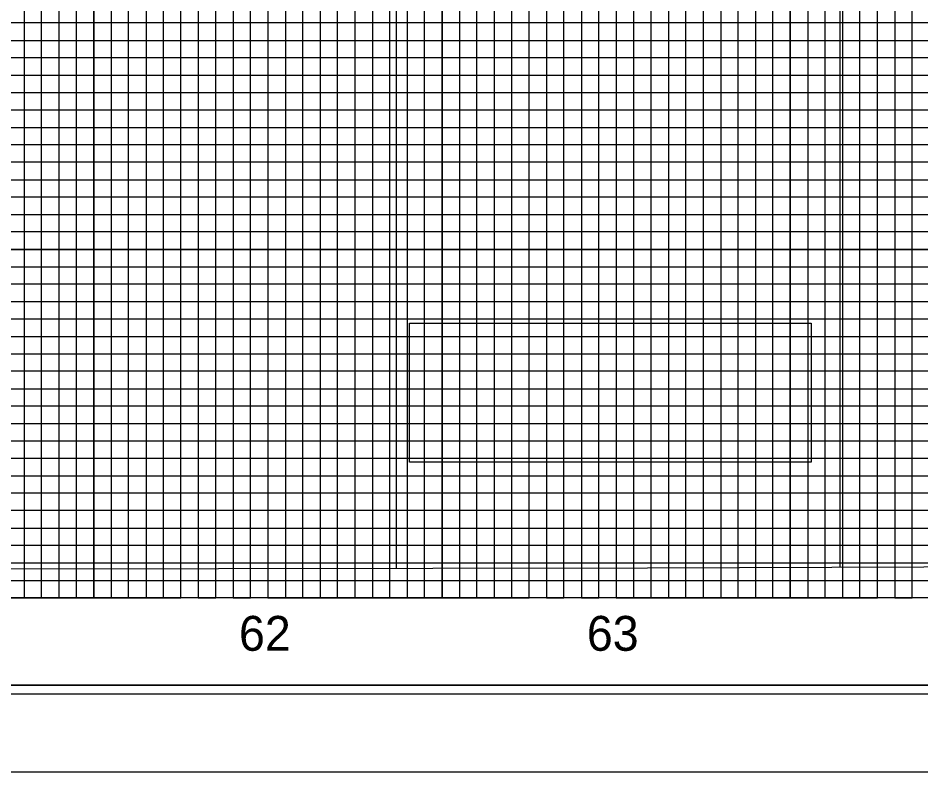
# Model space of a CAD drawing. Extents: x 557032 to 562069, y 513430 to 515874.
# Drawn here: x 558177.7 to 558437, y 514774.3 to 514990.7 of the extents above; entities that cross this region are included whole.
import ezdxf

# ---------------------------------------------------------------- set-up
doc = ezdxf.new("R2010")
doc.units = 0
for name, color, linetype in [('Exist Vertical Profile Horizontal Axis Label Major', 7, 'Continuous'), ('Prop Vertical Profile Curve Label', 7, 'Continuous'), ('Scratch_Level_1', 7, 'Continuous'), ('Scratch_Level_5', 7, 'Continuous'), ('Sheet Cutting Line CELL', 7, 'Continuous'), ('Sheet DOT Grid CELL', 7, 'Continuous'), ('Sheet Layout Profile Border Port 2', 7, 'Continuous'), ('Sheet Plot Border Inside CELL', 7, 'Continuous'), ('Sheet Plot Border Outside CELL', 7, 'Continuous'), ('Sheet Profile CELL', 7, 'Continuous'), ('Sheet Profile Grid Major CELL', 7, 'Continuous'), ('Sheet Profile Grid Middle CELL', 7, 'Continuous'), ('Sheet Profile Grid Minor CELL', 7, 'Continuous')]:
    doc.layers.add(name, color=color, linetype=linetype)

msp = doc.modelspace()

# ---------------------------------------------------------------- linework, layer by layer
at = {"layer": 'Prop Vertical Profile Curve Label'}
msp.add_lwpolyline([(558290.08, 514903.1), (558405.4, 514903.1), (558405.4, 514863.23), (558290.08, 514863.23)], close=True, dxfattribs=at)
at = {"layer": 'Scratch_Level_1'}
msp.add_line((558286.33, 514832.76), (558286.33, 515319), dxfattribs=at)
at = {"layer": 'Scratch_Level_5'}
msp.add_line((558413.73, 514833.08), (558413.73, 515318.28), dxfattribs=at)
msp.add_lwpolyline([(557249.45, 515324.28), (557249.45, 514824.28), (557239, 514812.71), (557236.95, 514799.28), (558647.93, 514799.13), (558699.45, 514799.28), (558649.45, 514824.28), (558649.45, 515324.28)], close=True, dxfattribs=at)
msp.add_lwpolyline([(557250.22, 514849.46), (558648.7, 514849.31), (558650.22, 514849.32)], dxfattribs=at)
at = {"layer": 'Sheet Cutting Line CELL'}
msp.add_line((557032.45, 514774.28), (558716.45, 514774.28), dxfattribs=at)
at = {"layer": 'Sheet DOT Grid CELL'}
for p, q in [((558199.45, 515324.28), (558199.45, 514824.28)), ((558249.45, 515324.28), (558249.45, 514824.28)), ((558299.45, 515324.28), (558299.45, 514824.28)), ((558349.45, 515324.28), (558349.45, 514824.28)), ((558399.45, 515324.28), (558399.45, 514824.28)), ((557199.45, 514974.28), (558699.34, 514974.28)), ((557199.45, 514924.28), (558699.34, 514924.28)), ((557199.45, 514874.28), (558699.34, 514874.28))]:
    msp.add_line(p, q, dxfattribs=at)
at = {"layer": 'Sheet Layout Profile Border Port 2'}
msp.add_lwpolyline([(557249.45, 515324.28), (558649.45, 515324.28), (558649.45, 514824.28), (557249.45, 514824.28)], close=True, dxfattribs=at)
msp.add_lwpolyline([(557249.45, 514831.1), (558358.41, 514832.88), (558649.45, 514833.95)], dxfattribs=at)
at = {"layer": 'Sheet Plot Border Inside CELL'}
msp.add_lwpolyline([(557045.45, 514796.73), (558711.95, 514796.73), (558711.95, 515851.83), (557045.45, 515851.83)], close=True, dxfattribs=at)
at = {"layer": 'Sheet Plot Border Outside CELL'}
msp.add_lwpolyline([(557032.45, 514774.28), (558716.45, 514774.28), (558716.45, 515874.28), (557032.45, 515874.28)], close=True, dxfattribs=at)
at = {"layer": 'Sheet Profile CELL'}
for p, q in [((558699.45, 514824.28), (557199.45, 514824.28)), ((557199.45, 514799.28), (558699.45, 514799.28))]:
    msp.add_line(p, q, dxfattribs=at)
msp.add_lwpolyline([(558699.45, 515849.28), (557199.45, 515849.28), (557199.45, 514799.28), (558699.45, 514799.28)], close=True, dxfattribs=at)
at = {"layer": 'Sheet Profile Grid Major CELL'}
for points in [[(558149.45, 514824.28), (558199.45, 514824.28), (558199.45, 515324.28), (558249.45, 515324.28), (558249.45, 514824.28), (558299.45, 514824.28), (558299.45, 515324.28), (558349.45, 515324.28), (558349.45, 514824.28), (558399.45, 514824.28), (558399.45, 515324.28), (558449.45, 515324.28), (558449.45, 514824.28), (558499.45, 514824.28), (558499.45, 515324.28), (558549.45, 515324.28), (558549.45, 514824.28), (558599.45, 514824.28), (558599.45, 514824.28), (558599.45, 514964.88)], [(558699.45, 515024.28), (557199.45, 515024.28), (557199.45, 514974.28), (558554.45, 514974.28)], [(558699.45, 514924.28), (557199.45, 514924.28), (557199.45, 514924.28), (557199.45, 514874.28), (558699.45, 514874.28)], [(558699.45, 514824.28), (557199.45, 514824.28)]]:
    msp.add_lwpolyline(points, dxfattribs=at)
at = {"layer": 'Sheet Profile Grid Middle CELL'}
for points in [[(558174.45, 514824.28), (558224.45, 514824.28), (558224.45, 515324.28), (558274.45, 515324.28), (558274.45, 514824.28), (558324.45, 514824.28), (558324.45, 515324.28), (558374.45, 515324.28), (558374.45, 514824.28), (558424.45, 514824.28), (558424.45, 515324.28), (558474.45, 515324.28), (558474.45, 514824.28), (558524.45, 514824.28), (558524.45, 515324.28), (558574.45, 515324.28), (558574.45, 514990.68)], [(558699.45, 514949.28), (557199.45, 514949.28), (557199.45, 514899.28), (558699.45, 514899.28)], [(558699.45, 514849.28), (557199.45, 514849.28)]]:
    msp.add_lwpolyline(points, dxfattribs=at)
at = {"layer": 'Sheet Profile Grid Minor CELL'}
for p, q in [((558554.45, 514989.28), (557249.45, 514989.28)), ((557249.45, 514984.28), (558554.45, 514984.28)), ((558554.45, 514979.28), (557249.45, 514979.28)), ((557249.45, 514969.28), (558554.45, 514969.28)), ((558649.45, 514964.28), (557249.45, 514964.28)), ((557249.45, 514959.28), (558649.45, 514959.28)), ((558649.45, 514954.28), (557249.45, 514954.28)), ((557249.45, 514944.28), (558649.45, 514944.28)), ((558649.45, 514939.28), (557249.45, 514939.28)), ((557249.45, 514934.28), (558649.45, 514934.28)), ((558649.45, 514929.28), (557249.45, 514929.28)), ((557249.45, 514919.28), (558649.45, 514919.28)), ((558649.45, 514914.28), (557249.45, 514914.28)), ((557249.45, 514909.28), (558649.45, 514909.28)), ((558649.45, 514904.28), (557249.45, 514904.28)), ((557249.45, 514894.28), (558649.45, 514894.28)), ((558649.45, 514889.28), (557249.45, 514889.28)), ((557249.45, 514884.28), (558649.45, 514884.28)), ((558649.45, 514879.28), (557249.45, 514879.28)), ((557249.45, 514869.28), (558649.45, 514869.28)), ((558649.45, 514864.28), (557249.45, 514864.28)), ((557249.45, 514859.28), (558649.45, 514859.28)), ((558649.45, 514854.28), (557249.45, 514854.28)), ((557249.45, 514844.28), (558649.45, 514844.28)), ((558649.45, 514839.28), (557249.45, 514839.28)), ((557249.45, 514834.28), (558649.45, 514834.28)), ((557249.45, 514829.28), (558649.45, 514829.28))]:
    msp.add_line(p, q, dxfattribs=at)
for points in [[(558179.45, 515324.28), (558179.45, 514824.28), (558184.45, 514824.28), (558184.45, 515324.28)], [(558189.45, 515324.28), (558189.45, 514824.28), (558194.45, 514824.28), (558194.45, 515324.28)], [(558204.45, 515324.28), (558204.45, 514824.28), (558209.45, 514824.28), (558209.45, 515324.28)], [(558214.45, 515324.28), (558214.45, 514824.28), (558219.45, 514824.28), (558219.45, 515324.28)], [(558229.45, 515324.28), (558229.45, 514824.28), (558234.45, 514824.28), (558234.45, 515324.28)], [(558239.45, 515324.28), (558239.45, 514824.28), (558244.45, 514824.28), (558244.45, 515324.28)], [(558254.45, 515324.28), (558254.45, 514824.28), (558259.45, 514824.28), (558259.45, 515324.28)], [(558264.45, 515324.28), (558264.45, 514824.28), (558269.45, 514824.28), (558269.45, 515324.28)], [(558279.45, 515324.28), (558279.45, 514824.28), (558284.45, 514824.28), (558284.45, 515324.28)], [(558289.45, 515324.28), (558289.45, 514824.28), (558294.45, 514824.28), (558294.45, 515324.28)], [(558304.45, 515324.28), (558304.45, 514824.28), (558309.45, 514824.28), (558309.45, 515324.28)], [(558314.45, 515324.28), (558314.45, 514824.28), (558319.45, 514824.28), (558319.45, 515324.28)], [(558329.45, 515324.28), (558329.45, 514824.28), (558334.45, 514824.28), (558334.45, 515324.28)], [(558339.45, 515324.28), (558339.45, 514824.28), (558344.45, 514824.28), (558344.45, 515324.28)], [(558354.45, 515324.28), (558354.45, 514824.28), (558359.45, 514824.28), (558359.45, 515324.28)], [(558364.45, 515324.28), (558364.45, 514824.28), (558369.45, 514824.28), (558369.45, 515324.28)], [(558379.45, 515324.28), (558379.45, 514824.28), (558384.45, 514824.28), (558384.45, 515324.28)], [(558389.45, 515324.28), (558389.45, 514824.28)], [(558389.45, 514824.28), (558394.45, 514824.28), (558394.45, 515324.28)], [(558404.45, 515324.28), (558404.45, 514824.28), (558409.45, 514824.28), (558409.45, 515324.28)], [(558414.45, 515324.28), (558414.45, 514824.28), (558419.45, 514824.28), (558419.45, 515324.28)], [(558429.45, 515324.28), (558429.45, 514824.28), (558434.45, 514824.28), (558434.45, 515324.28)]]:
    msp.add_lwpolyline(points, dxfattribs=at)

# ---------------------------------------------------------------- texts
at = {"layer": 'Exist Vertical Profile Horizontal Axis Label Major'}
for s, p in [('62', (558241.13, 514809.06)), ('63', (558341.02, 514809.06))]:
    msp.add_text(s, height=10, dxfattribs=at).set_placement(p)

doc.saveas('drawing.dxf')
